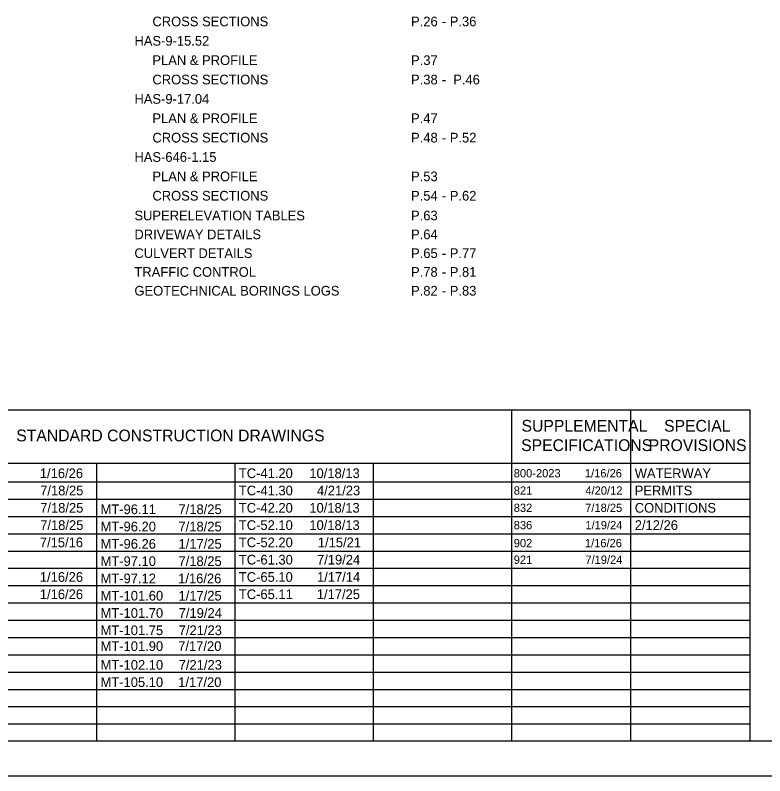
# Model space of a CAD drawing. Extents: x 0 to 34, y -32.5 to 22.
# Drawn here: x 12.97 to 23.81, y 0 to 11 of the extents above; entities that cross this region are included whole.
import ezdxf

# ---------------------------------------------------------------- set-up
doc = ezdxf.new("R2010")
doc.units = 0
for name, color, linetype in [('GM_X_Adjacent_County', 7, 'Continuous'), ('GM_X_County', 7, 'Continuous'), ('GM_X_Section', 7, 'Continuous'), ('GM_X_Township', 7, 'Continuous')]:
    doc.layers.add(name, color=color, linetype=linetype)

msp = doc.modelspace()

# ---------------------------------------------------------------- linework, layer by layer
at = {"layer": 'GM_X_County'}
msp.add_lwpolyline([(1.5, 21.5), (33.5, 21.5), (33.5, 0.5), (1.5, 0.5)], close=True, dxfattribs=at)
at = {"layer": 'GM_X_Section'}
msp.add_lwpolyline([(0, 0), (34, 0), (34, 22), (0, 22)], close=True, dxfattribs=at)
at = {"layer": 'GM_X_Township'}
for p, q in [((10.15, 5.292), (23.6, 5.292)), ((20.15, 0.5), (20.15, 5.292)), ((21.875, 0.5), (21.875, 5.292)), ((23.6, 0.5), (23.6, 5.292)), ((10.15, 4.521), (23.6, 4.521)), ((14.15, 0.5), (14.15, 4.521)), ((16.15, 0.5), (16.15, 4.521)), ((18.15, 0.5), (18.15, 4.521)), ((10.15, 4.25), (23.6, 4.25)), ((10.15, 4), (23.6, 4)), ((10.15, 3.75), (23.6, 3.75)), ((10.15, 3.5), (23.6, 3.5)), ((10.15, 3.25), (23.6, 3.25)), ((10.15, 3), (23.6, 3)), ((10.15, 2.75), (23.6, 2.75)), ((10.15, 2.5), (23.6, 2.5)), ((10.15, 2.25), (23.6, 2.25)), ((10.15, 2), (23.6, 2)), ((10.15, 1.75), (23.6, 1.75)), ((10.15, 1.5), (23.6, 1.5)), ((10.15, 1.25), (23.6, 1.25)), ((10.15, 1), (23.6, 1)), ((10.15, 0.75), (23.6, 0.75))]:
    msp.add_line(p, q, dxfattribs=at)

# ---------------------------------------------------------------- texts
at = {"layer": 'GM_X_Adjacent_County'}
for s, height, p in [('     CROSS SECTIONS', 0.14, (14.695, 10.838)), ('P.26', 0.14, (18.695, 10.838)), (' - ', 0.14, (19.088, 10.838)), ('P.36', 0.14, (19.255, 10.838)), ('HAS-9-15.52', 0.14, (14.695, 10.558)), ('     PLAN & PROFILE', 0.14, (14.695, 10.278)), ('P.37', 0.14, (18.695, 10.278)), ('     CROSS SECTIONS', 0.14, (14.695, 9.998)), ('P.38', 0.14, (18.695, 9.998)), ('P.46', 0.14, (19.305, 9.998)), (' - ', 0.14, (19.088, 9.998)), ('HAS-9-17.04', 0.14, (14.695, 9.718)), ('     PLAN & PROFILE', 0.14, (14.695, 9.438)), ('P.47', 0.14, (18.695, 9.438)), ('     CROSS SECTIONS', 0.14, (14.695, 9.158)), ('P.48', 0.14, (18.695, 9.158)), ('P.52', 0.14, (19.255, 9.158)), (' - ', 0.14, (19.088, 9.158)), ('HAS-646-1.15', 0.14, (14.695, 8.878)), ('     PLAN & PROFILE', 0.14, (14.695, 8.598)), ('P.53', 0.14, (18.695, 8.598)), ('     CROSS SECTIONS', 0.14, (14.695, 8.318)), ('P.54', 0.14, (18.695, 8.318)), (' - ', 0.14, (19.088, 8.318)), ('P.62', 0.14, (19.255, 8.318)), ('SUPERELEVATION TABLES', 0.14, (14.695, 8.032)), ('P.63', 0.14, (18.695, 8.032)), ('DRIVEWAY DETAILS', 0.14, (14.695, 7.759)), ('P.64', 0.14, (18.695, 7.759)), ('CULVERT DETAILS', 0.14, (14.695, 7.487)), ('P.65', 0.14, (18.695, 7.487)), ('P.77', 0.14, (19.255, 7.487)), (' - ', 0.14, (19.088, 7.487)), ('TRAFFIC CONTROL', 0.14, (14.695, 7.216)), ('P.78', 0.14, (18.695, 7.216)), (' - ', 0.14, (19.088, 7.216)), ('P.81', 0.14, (19.255, 7.216)), ('GEOTECHNICAL BORINGS LOGS', 0.14, (14.695, 6.944)), ('P.82', 0.14, (18.695, 6.944)), ('P.83', 0.14, (19.255, 6.944)), (' - ', 0.14, (19.088, 6.944)), ('SUPPLEMENTAL', 0.17, (20.293, 4.976)), ('SPECIAL', 0.17, (22.354, 4.976)), ('STANDARD CONSTRUCTION DRAWINGS', 0.17, (12.986, 4.836)), ('SPECIFICATIONS', 0.17, (20.287, 4.696)), ('PROVISIONS', 0.17, (22.132, 4.696)), ('1/16/26', 0.14, (13.327, 4.305)), ('TC-41.20', 0.14, (16.205, 4.305)), ('10/18/13', 0.14, (17.224, 4.305)), ('800-2023', 0.12, (20.18, 4.315)), ('1/16/26', 0.12, (21.209, 4.315)), ('WATERWAY', 0.14, (21.93, 4.305)), ('7/18/25', 0.14, (13.332, 4.055)), ('TC-41.30', 0.14, (16.205, 4.055)), ('4/21/23', 0.14, (17.335, 4.055)), ('821', 0.12, (20.18, 4.065)), ('4/20/12', 0.12, (21.216, 4.065)), ('PERMITS', 0.14, (21.93, 4.055)), ('7/18/25', 0.14, (13.332, 3.805)), ('MT-96.11', 0.14, (14.205, 3.784)), ('7/18/25', 0.14, (15.332, 3.784)), ('TC-42.20', 0.14, (16.205, 3.805)), ('10/18/13', 0.14, (17.224, 3.805)), ('832', 0.12, (20.18, 3.815)), ('7/18/25', 0.12, (21.213, 3.815)), ('CONDITIONS', 0.14, (21.93, 3.805)), ('7/18/25', 0.14, (13.332, 3.555)), ('MT-96.20', 0.14, (14.205, 3.534)), ('7/18/25', 0.14, (15.332, 3.534)), ('TC-52.10', 0.14, (16.205, 3.555)), ('10/18/13', 0.14, (17.224, 3.555)), ('836', 0.12, (20.18, 3.565)), ('1/19/24', 0.12, (21.216, 3.565)), ('2/12/26', 0.14, (21.93, 3.555)), ('7/15/16', 0.14, (13.327, 3.305)), ('MT-96.26', 0.14, (14.205, 3.284)), ('1/17/25', 0.14, (15.332, 3.284)), ('TC-52.20', 0.14, (16.205, 3.305)), ('1/15/21', 0.14, (17.347, 3.305)), ('902', 0.12, (20.18, 3.305)), ('1/16/26', 0.12, (21.209, 3.305)), ('TC-61.30', 0.14, (16.205, 3.055)), ('7/19/24', 0.14, (17.335, 3.055)), ('7/19/24', 0.12, (21.216, 3.065)), ('MT-97.10', 0.14, (14.205, 3.034)), ('7/18/25', 0.14, (15.332, 3.034)), ('921', 0.12, (20.18, 3.065)), ('1/16/26', 0.14, (13.327, 2.805)), ('MT-97.12', 0.14, (14.205, 2.784)), ('1/16/26', 0.14, (15.327, 2.784)), ('TC-65.10', 0.14, (16.205, 2.805)), ('1/17/14', 0.14, (17.335, 2.805)), ('1/16/26', 0.14, (13.327, 2.555)), ('MT-101.60', 0.14, (14.205, 2.534)), ('1/17/25', 0.14, (15.332, 2.534)), ('TC-65.11', 0.14, (16.205, 2.555)), ('1/17/25', 0.14, (17.332, 2.555)), ('MT-101.70', 0.14, (14.205, 2.284)), ('7/19/24', 0.14, (15.335, 2.284)), ('MT-101.75', 0.14, (14.205, 2.034)), ('7/21/23', 0.14, (15.335, 2.034)), ('MT-101.90', 0.14, (14.205, 1.805)), ('7/17/20', 0.14, (15.328, 1.805)), ('MT-102.10', 0.14, (14.205, 1.534)), ('7/21/23', 0.14, (15.335, 1.534)), ('1/17/20', 0.14, (15.328, 1.284)), ('MT-105.10', 0.14, (14.205, 1.284))]:
    msp.add_text(s, height=height, dxfattribs=at).set_placement(p)

doc.saveas('drawing.dxf')
